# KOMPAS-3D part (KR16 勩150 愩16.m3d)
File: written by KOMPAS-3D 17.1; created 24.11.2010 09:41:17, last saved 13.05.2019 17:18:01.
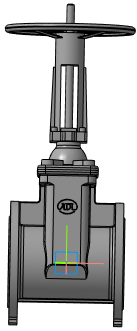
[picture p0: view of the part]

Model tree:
1. Плоскость XY
2. Плоскость ZX
3. Плоскость ZY
4. Ось X
5. Ось Y
6. Ось Z
7. Начало координат
8. Операция без истории:2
